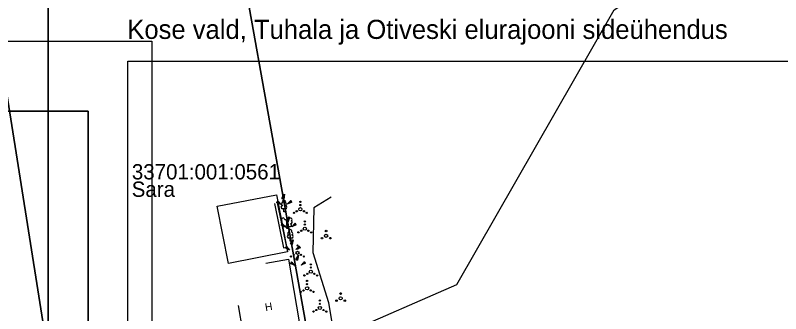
# Model space of a CAD drawing. Extents: x 554947 to 555436, y 6564938 to 6565792.
# Drawn here: x 555187.9 to 555307.9, y 6565612.2 to 6565659 of the extents above; entities that cross this region are included whole.
import ezdxf

# ---------------------------------------------------------------- set-up
doc = ezdxf.new("R2010")
doc.units = 0
for name, color, linetype in [('AED', 7, 'Continuous'), ('HALJASTUS', 7, 'Continuous'), ('HOONE', 7, 'Continuous'), ('Hoone Vare', 7, 'Continuous'), ('PIIR', 7, 'Continuous'), ('PR_SIDE', 7, 'Continuous'), ('PUU', 7, 'Continuous'), ('RELJEEF', 7, 'Continuous'), ('VORMISTUS_2', 7, 'Continuous'), ('VORMISTUS_3', 7, 'Continuous')]:
    doc.layers.add(name, color=color, linetype=linetype)

msp = doc.modelspace()

# ---------------------------------------------------------------- linework, layer by layer
at = {"layer": 'AED'}
msp.add_lwpolyline([(555228.56, 6565629.44), (555229.99, 6565622.5), (555230.48, 6565622.6), (555229.05, 6565629.54)], dxfattribs=at)
at = {"layer": 'HALJASTUS'}
msp.add_lwpolyline([(555237.45, 6565630.43), (555234.71, 6565628.77), (555234.59, 6565621.78), (555237.04, 6565613.92), (555237.94, 6565608.22), (555242.28, 6565610.46)], dxfattribs=at)
for centre, radius in [((555232.61, 6565629.7), 0.1), ((555232.05, 6565628.23), 0.1), ((555232.61, 6565628.55), 0.25), ((555232.61, 6565629.2), 0.1), ((555233.18, 6565628.23), 0.1), ((555231.61, 6565627.98), 0.1), ((555233.61, 6565627.98), 0.1), ((555233.31, 6565626.64), 0.1), ((555233.31, 6565626.14), 0.1), ((555232.31, 6565624.92), 0.1), ((555232.75, 6565625.17), 0.1), ((555233.31, 6565625.49), 0.25), ((555233.88, 6565625.17), 0.1), ((555234.31, 6565624.92), 0.1), ((555232.16, 6565622.86), 0.1), ((555232.16, 6565622.36), 0.1), ((555231.16, 6565621.14), 0.1), ((555231.59, 6565621.39), 0.1), ((555232.16, 6565621.71), 0.25), ((555232.72, 6565621.39), 0.1), ((555233.16, 6565621.14), 0.1), ((555234.25, 6565619.9), 0.1), ((555234.25, 6565618.75), 0.25), ((555234.25, 6565619.4), 0.1), ((555233.25, 6565618.17), 0.1), ((555233.69, 6565618.42), 0.1), ((555234.82, 6565618.42), 0.1), ((555235.25, 6565618.17), 0.1), ((555233.67, 6565616.15), 0.25), ((555233.67, 6565617.3), 0.1), ((555233.67, 6565616.8), 0.1), ((555232.67, 6565615.57), 0.1), ((555233.11, 6565615.82), 0.1), ((555234.24, 6565615.82), 0.1), ((555234.67, 6565615.57), 0.1), ((555235.67, 6565614.21), 0.1), ((555235.11, 6565612.74), 0.1), ((555235.67, 6565613.06), 0.25), ((555235.67, 6565613.71), 0.1), ((555236.24, 6565612.74), 0.1), ((555234.67, 6565612.49), 0.1), ((555236.67, 6565612.49), 0.1)]:
    msp.add_circle(centre, radius, dxfattribs=at)
at = {"layer": 'HOONE'}
msp.add_lwpolyline([(555227.21, 6565620.08), (555230.73, 6565620.69), (555232.44, 6565610.91), (555223.59, 6565609.46), (555222.94, 6565613.43)], dxfattribs=at)
at = {"layer": 'Hoone Vare'}
msp.add_lwpolyline([(555230.6, 6565621.87), (555221.34, 6565620.06), (555219.59, 6565629.02), (555228.86, 6565630.83)], close=True, dxfattribs=at)
at = {"layer": 'PIIR'}
msp.add_lwpolyline([(555193.24, 6565604.68), (555183.94, 6565663.24), (555223.17, 6565668.21), (555234.35, 6565605.6), (555225.47, 6565605.89), (555193.7, 6565602.7)], close=True, dxfattribs=at)
for points in [[(555374.15, 6565660.24), (555410.9, 6565638.65), (555418.94, 6565635.85), (555435.71, 6565632.72), (555428.83, 6565620.98), (555419.65, 6565609.54), (555361.56, 6565549.57), (555350.68, 6565540.44), (555343.81, 6565536.56), (555330.71, 6565538.85), (555251.24, 6565598.48), (555234.35, 6565605.6), (555223.17, 6565668.21)], [(555183.94, 6565663.24), (555193.24, 6565604.68), (555160.12, 6565598.86)]]:
    msp.add_lwpolyline(points, dxfattribs=at)
at = {"layer": 'PR_SIDE'}
msp.add_lwpolyline([(555232.4, 6565605.17), (555232.48, 6565605.3), (555234.36, 6565605.15), (555239.41, 6565608.98), (555257.15, 6565616.75), (555281.8, 6565659.83), (555291.68, 6565666.13), (555336.53, 6565656.68), (555340.55, 6565660.53)], dxfattribs=at)
at = {"layer": 'PUU'}
for p, q in [((555230.28, 6565628.63), (555229.8, 6565628.63)), ((555230.04, 6565628.15), (555230.04, 6565628.63)), ((555230.42, 6565628.15), (555230.04, 6565628.15)), ((555230.03, 6565625.84), (555230.47, 6565626.01)), ((555230.47, 6565625.5), (555230.29, 6565625.94)), ((555230.47, 6565626.01), (555230.91, 6565625.83)), ((555230.47, 6565625.5), (555230.65, 6565625.94)), ((555230.85, 6565625.5), (555230.47, 6565625.5)), ((555231.27, 6565624.03), (555230.79, 6565624.03)), ((555231.03, 6565623.55), (555231.03, 6565624.03)), ((555231.41, 6565623.55), (555231.03, 6565623.55))]:
    msp.add_line(p, q, dxfattribs=at)
msp.add_lwpolyline([(555230.47, 6565626.51), (555230.45, 6565626.43), (555230.45, 6565626.41), (555230.46, 6565626.38), (555230.48, 6565626.35), (555230.49, 6565626.33), (555230.47, 6565626.29), (555230.45, 6565626.24), (555230.44, 6565626.22), (555230.45, 6565626.2), (555230.46, 6565626.17), (555230.49, 6565626.11), (555230.5, 6565626.09), (555230.49, 6565626.07), (555230.48, 6565626.04), (555230.47, 6565626.01)], dxfattribs=at)
for centre, radius in [((555236.65, 6565625.13), 0.125), ((555235.99, 6565624.01), 0.125), ((555236.65, 6565624.38), 0.25), ((555237.3, 6565624.01), 0.125), ((555238.93, 6565615.32), 0.125), ((555238.28, 6565614.2), 0.125), ((555238.93, 6565614.57), 0.25), ((555239.58, 6565614.2), 0.125)]:
    msp.add_circle(centre, radius, dxfattribs=at)
for centre, radius, start, end in [((555229.87, 6565629.33), 0.233, 109.0217, 253.1415), ((555230.04, 6565629.67), 0.277, 332.5799, 207.4201), ((555230.21, 6565629.33), 0.233, 286.8508, 70.9859), ((555229.81, 6565628.87), 0.238, 90.0016, 269.3953), ((555230.28, 6565628.87), 0.238, 270.6047, 89.9984), ((555229.91, 6565626.92), 0.256, 111.5027, 232.5173), ((555229.91, 6565626.92), 0.256, 350.4856, 111.5002), ((555231.05, 6565626.91), 0.256, 67.6168, 188.6314), ((555231.05, 6565626.91), 0.256, 306.5997, 67.6143), ((555229.84, 6565626.51), 0.224, 111.4304, 274.4987), ((555229.94, 6565626.06), 0.237, 111.5014, 291.5004), ((555230.25, 6565626.67), 0.224, 308.5041, 111.5725), ((555230.47, 6565626.27), 0.237, 66.7655, 111.5015), ((555230.71, 6565626.66), 0.225, 67.7016, 230.5126), ((555231, 6565626.06), 0.237, 247.6166, 67.6155), ((555231.11, 6565626.5), 0.224, 264.6183, 67.6866), ((555230.86, 6565624.73), 0.233, 109.0217, 253.1415), ((555231.03, 6565625.07), 0.277, 332.5799, 207.4201), ((555231.2, 6565624.73), 0.233, 286.8508, 70.9859), ((555230.8, 6565624.27), 0.238, 90.0016, 269.3953), ((555231.27, 6565624.27), 0.238, 270.6047, 89.9984)]:
    msp.add_arc(centre, radius, start, end, dxfattribs=at)
at = {"layer": 'RELJEEF'}
for p, q in [((555229.72, 6565630.25), (555230.14, 6565630.89)), ((555229.97, 6565630.63), (555230.1, 6565630.69)), ((555230.14, 6565630.89), (555230, 6565630.14)), ((555230.02, 6565630.7), (555230.12, 6565630.74)), ((555230.07, 6565630.78), (555230.13, 6565630.8)), ((555230.12, 6565630.85), (555230.14, 6565630.86)), ((555229.08, 6565629.85), (555228.9, 6565629.61)), ((555229.59, 6565629.28), (555228.9, 6565629.61)), ((555228.91, 6565629.63), (555228.91, 6565629.61)), ((555228.95, 6565629.68), (555228.97, 6565629.58)), ((555229, 6565629.74), (555229.02, 6565629.56)), ((555229.04, 6565629.8), (555229.07, 6565629.53)), ((555229.08, 6565629.85), (555229.59, 6565629.28)), ((555229.08, 6565629.85), (555229.13, 6565629.5)), ((555229.08, 6565629.85), (555229.08, 6565629.85)), ((555229.14, 6565629.79), (555229.18, 6565629.48)), ((555229.2, 6565629.72), (555229.24, 6565629.45)), ((555229.26, 6565629.65), (555229.28, 6565629.51)), ((555229.28, 6565629.51), (555229.29, 6565629.42)), ((555229.32, 6565629.58), (555229.35, 6565629.4)), ((555229.38, 6565629.52), (555229.4, 6565629.37)), ((555229.72, 6565630.25), (555230.05, 6565630.39)), ((555229.72, 6565630.25), (555230, 6565630.14)), ((555229.72, 6565630.25), (555229.72, 6565630.25)), ((555229.77, 6565630.33), (555230.06, 6565630.45)), ((555229.79, 6565630.23), (555230.04, 6565630.33)), ((555229.82, 6565630.4), (555230.07, 6565630.51)), ((555229.85, 6565630.2), (555230.03, 6565630.27)), ((555229.87, 6565630.48), (555230, 6565630.53)), ((555229.92, 6565630.55), (555230.09, 6565630.63)), ((555229.92, 6565630.17), (555230.02, 6565630.21)), ((555229.99, 6565630.15), (555230, 6565630.15)), ((555230, 6565630.53), (555230.08, 6565630.57)), ((555230.56, 6565629.35), (555231.1, 6565629.89)), ((555231.27, 6565629.64), (555230.56, 6565629.35)), ((555230.85, 6565629.47), (555230.71, 6565629.5)), ((555230.94, 6565629.5), (555230.75, 6565629.54)), ((555230.89, 6565629.56), (555230.8, 6565629.58)), ((555231.1, 6565629.57), (555230.84, 6565629.62)), ((555231.19, 6565629.61), (555230.88, 6565629.67)), ((555231.02, 6565629.54), (555230.89, 6565629.56)), ((555231.27, 6565629.64), (555230.92, 6565629.71)), ((555231.23, 6565629.7), (555230.97, 6565629.75)), ((555231.19, 6565629.76), (555231.01, 6565629.79)), ((555231.15, 6565629.82), (555231.05, 6565629.84)), ((555231.11, 6565629.88), (555231.09, 6565629.88)), ((555231.27, 6565629.64), (555231.1, 6565629.89)), ((555231.27, 6565629.64), (555231.27, 6565629.64)), ((555229.44, 6565629.45), (555229.45, 6565629.35)), ((555229.5, 6565629.38), (555229.51, 6565629.32)), ((555229.56, 6565629.31), (555229.56, 6565629.29)), ((555230.6, 6565629.36), (555230.59, 6565629.37)), ((555230.69, 6565629.4), (555230.63, 6565629.41)), ((555230.77, 6565629.43), (555230.67, 6565629.45)), ((555230.42, 6565626.71), (555230.84, 6565627.35)), ((555230.62, 6565627.01), (555230.79, 6565627.08)), ((555230.67, 6565627.08), (555230.8, 6565627.14)), ((555230.84, 6565627.35), (555230.7, 6565626.59)), ((555230.72, 6565627.16), (555230.82, 6565627.2)), ((555230.77, 6565627.23), (555230.83, 6565627.26)), ((555230.82, 6565627.31), (555230.84, 6565627.32)), ((555229.78, 6565626.3), (555229.6, 6565626.06)), ((555230.29, 6565625.73), (555229.6, 6565626.06)), ((555229.61, 6565626.08), (555229.61, 6565626.06)), ((555229.65, 6565626.13), (555229.67, 6565626.03)), ((555229.7, 6565626.19), (555229.72, 6565626.01)), ((555229.74, 6565626.25), (555229.77, 6565625.98)), ((555229.78, 6565626.3), (555230.29, 6565625.73)), ((555229.78, 6565626.3), (555229.83, 6565625.95)), ((555229.78, 6565626.3), (555229.78, 6565626.3)), ((555229.84, 6565626.24), (555229.88, 6565625.93)), ((555229.9, 6565626.17), (555229.94, 6565625.9)), ((555229.96, 6565626.1), (555229.98, 6565625.96)), ((555229.98, 6565625.96), (555229.99, 6565625.87)), ((555230.02, 6565626.03), (555230.05, 6565625.85)), ((555230.08, 6565625.97), (555230.1, 6565625.82)), ((555230.14, 6565625.9), (555230.15, 6565625.8)), ((555230.42, 6565626.71), (555230.75, 6565626.85)), ((555230.42, 6565626.71), (555230.7, 6565626.59)), ((555230.42, 6565626.71), (555230.42, 6565626.71)), ((555230.47, 6565626.78), (555230.76, 6565626.9)), ((555230.49, 6565626.68), (555230.74, 6565626.79)), ((555230.52, 6565626.86), (555230.77, 6565626.96)), ((555230.55, 6565626.65), (555230.73, 6565626.73)), ((555230.57, 6565626.93), (555230.7, 6565626.99)), ((555230.62, 6565626.63), (555230.72, 6565626.67)), ((555230.69, 6565626.6), (555230.7, 6565626.61)), ((555230.7, 6565626.99), (555230.78, 6565627.02)), ((555231.26, 6565625.8), (555231.8, 6565626.34)), ((555231.97, 6565626.09), (555231.26, 6565625.8)), ((555231.47, 6565625.88), (555231.37, 6565625.9)), ((555231.55, 6565625.92), (555231.41, 6565625.95)), ((555231.64, 6565625.95), (555231.45, 6565625.99)), ((555231.59, 6565626.01), (555231.5, 6565626.03)), ((555231.8, 6565626.02), (555231.54, 6565626.07)), ((555231.89, 6565626.06), (555231.58, 6565626.12)), ((555231.72, 6565625.99), (555231.59, 6565626.01)), ((555231.97, 6565626.09), (555231.62, 6565626.16)), ((555231.93, 6565626.15), (555231.67, 6565626.2)), ((555231.89, 6565626.21), (555231.71, 6565626.24)), ((555231.85, 6565626.27), (555231.75, 6565626.29)), ((555231.81, 6565626.33), (555231.79, 6565626.33)), ((555231.97, 6565626.09), (555231.8, 6565626.34)), ((555231.97, 6565626.09), (555231.97, 6565626.09)), ((555230.2, 6565625.83), (555230.21, 6565625.77)), ((555230.26, 6565625.76), (555230.26, 6565625.74)), ((555231.3, 6565625.81), (555231.29, 6565625.82)), ((555231.39, 6565625.85), (555231.33, 6565625.86)), ((555231.07, 6565623.12), (555231.49, 6565623.76)), ((555231.27, 6565623.42), (555231.44, 6565623.49)), ((555231.32, 6565623.49), (555231.45, 6565623.55)), ((555231.49, 6565623.76), (555231.35, 6565623)), ((555231.36, 6565623.57), (555231.46, 6565623.61)), ((555231.41, 6565623.64), (555231.47, 6565623.67)), ((555231.46, 6565623.72), (555231.48, 6565623.73)), ((555230.42, 6565622.72), (555230.24, 6565622.48)), ((555230.93, 6565622.15), (555230.24, 6565622.48)), ((555230.25, 6565622.49), (555230.25, 6565622.47)), ((555230.29, 6565622.55), (555230.31, 6565622.45)), ((555230.34, 6565622.61), (555230.36, 6565622.42)), ((555230.38, 6565622.66), (555230.41, 6565622.39)), ((555230.42, 6565622.72), (555230.93, 6565622.15)), ((555230.42, 6565622.72), (555230.47, 6565622.37)), ((555230.42, 6565622.72), (555230.42, 6565622.72)), ((555230.48, 6565622.65), (555230.52, 6565622.34)), ((555230.54, 6565622.58), (555230.58, 6565622.32)), ((555230.6, 6565622.52), (555230.62, 6565622.38)), ((555230.62, 6565622.38), (555230.63, 6565622.29)), ((555230.66, 6565622.45), (555230.69, 6565622.26)), ((555230.72, 6565622.38), (555230.74, 6565622.24)), ((555230.78, 6565622.31), (555230.79, 6565622.21)), ((555231.07, 6565623.12), (555231.39, 6565623.26)), ((555231.07, 6565623.12), (555231.35, 6565623)), ((555231.07, 6565623.12), (555231.07, 6565623.12)), ((555231.12, 6565623.19), (555231.4, 6565623.31)), ((555231.13, 6565623.09), (555231.38, 6565623.2)), ((555231.17, 6565623.27), (555231.42, 6565623.37)), ((555231.2, 6565623.06), (555231.37, 6565623.14)), ((555231.22, 6565623.34), (555231.34, 6565623.4)), ((555231.27, 6565623.04), (555231.36, 6565623.08)), ((555231.33, 6565623.01), (555231.35, 6565623.02)), ((555231.34, 6565623.4), (555231.43, 6565623.43)), ((555231.9, 6565622.21), (555232.44, 6565622.76)), ((555232.61, 6565622.51), (555231.9, 6565622.21)), ((555232.03, 6565622.26), (555231.97, 6565622.28)), ((555232.11, 6565622.3), (555232.01, 6565622.32)), ((555232.19, 6565622.33), (555232.05, 6565622.36)), ((555232.28, 6565622.37), (555232.09, 6565622.4)), ((555232.23, 6565622.43), (555232.14, 6565622.45)), ((555232.44, 6565622.44), (555232.18, 6565622.49)), ((555232.53, 6565622.47), (555232.22, 6565622.53)), ((555232.36, 6565622.4), (555232.23, 6565622.43)), ((555232.61, 6565622.51), (555232.26, 6565622.57)), ((555232.57, 6565622.56), (555232.31, 6565622.62)), ((555232.53, 6565622.62), (555232.35, 6565622.66)), ((555232.49, 6565622.68), (555232.39, 6565622.7)), ((555232.45, 6565622.74), (555232.43, 6565622.74)), ((555232.61, 6565622.51), (555232.44, 6565622.76)), ((555232.61, 6565622.51), (555232.61, 6565622.51)), ((555230.84, 6565622.25), (555230.85, 6565622.18)), ((555230.9, 6565622.18), (555230.9, 6565622.16)), ((555231.89, 6565620.68), (555232.31, 6565621.32)), ((555231.94, 6565622.23), (555231.93, 6565622.23)), ((555232.14, 6565621.06), (555232.27, 6565621.12)), ((555232.31, 6565621.32), (555232.17, 6565620.57)), ((555232.19, 6565621.13), (555232.29, 6565621.17)), ((555232.24, 6565621.21), (555232.3, 6565621.23)), ((555232.29, 6565621.28), (555232.31, 6565621.29)), ((555231.25, 6565620.28), (555231.06, 6565620.04)), ((555231.75, 6565619.71), (555231.06, 6565620.04)), ((555231.07, 6565620.06), (555231.08, 6565620.04)), ((555231.12, 6565620.11), (555231.13, 6565620.01)), ((555231.16, 6565620.17), (555231.19, 6565619.99)), ((555231.2, 6565620.23), (555231.24, 6565619.96)), ((555231.25, 6565620.28), (555231.75, 6565619.71)), ((555231.25, 6565620.28), (555231.29, 6565619.93)), ((555231.25, 6565620.28), (555231.25, 6565620.28)), ((555231.31, 6565620.22), (555231.35, 6565619.91)), ((555231.37, 6565620.15), (555231.4, 6565619.88)), ((555231.43, 6565620.08), (555231.44, 6565619.94)), ((555231.44, 6565619.94), (555231.46, 6565619.85)), ((555231.48, 6565620.01), (555231.51, 6565619.83)), ((555231.54, 6565619.95), (555231.56, 6565619.8)), ((555231.6, 6565619.88), (555231.62, 6565619.78)), ((555231.89, 6565620.68), (555232.22, 6565620.82)), ((555231.89, 6565620.68), (555232.17, 6565620.57)), ((555231.89, 6565620.68), (555231.89, 6565620.68)), ((555231.94, 6565620.76), (555232.23, 6565620.88)), ((555231.96, 6565620.66), (555232.21, 6565620.76)), ((555231.99, 6565620.83), (555232.24, 6565620.94)), ((555232.02, 6565620.63), (555232.2, 6565620.7)), ((555232.04, 6565620.91), (555232.17, 6565620.96)), ((555232.09, 6565620.98), (555232.26, 6565621.06)), ((555232.09, 6565620.6), (555232.19, 6565620.64)), ((555232.16, 6565620.58), (555232.17, 6565620.58)), ((555232.17, 6565620.96), (555232.25, 6565621)), ((555232.73, 6565619.78), (555233.27, 6565620.32)), ((555233.44, 6565620.07), (555232.73, 6565619.78)), ((555232.94, 6565619.86), (555232.83, 6565619.88)), ((555233.02, 6565619.9), (555232.88, 6565619.93)), ((555233.1, 6565619.93), (555232.92, 6565619.97)), ((555233.05, 6565619.99), (555232.96, 6565620.01)), ((555233.27, 6565620), (555233, 6565620.05)), ((555233.35, 6565620.04), (555233.05, 6565620.1)), ((555233.19, 6565619.97), (555233.05, 6565619.99)), ((555233.44, 6565620.07), (555233.09, 6565620.14)), ((555233.4, 6565620.13), (555233.13, 6565620.18)), ((555233.36, 6565620.19), (555233.17, 6565620.22)), ((555233.32, 6565620.25), (555233.22, 6565620.27)), ((555233.28, 6565620.31), (555233.26, 6565620.31)), ((555233.44, 6565620.07), (555233.27, 6565620.32)), ((555233.44, 6565620.07), (555233.44, 6565620.07)), ((555231.66, 6565619.81), (555231.67, 6565619.75)), ((555231.72, 6565619.74), (555231.73, 6565619.72)), ((555232.77, 6565619.79), (555232.75, 6565619.8)), ((555232.85, 6565619.83), (555232.79, 6565619.84))]:
    msp.add_line(p, q, dxfattribs=at)
at = {"layer": 'VORMISTUS_2'}
for points in [[(554999.36, 6565654.91), (555209.36, 6565654.91), (555209.36, 6565357.91), (554999.36, 6565357.91)], [(555009.36, 6565368.91), (555199.36, 6565368.91), (555199.36, 6565643.91), (555009.36, 6565643.91)], [(555009.36, 6565643.91), (555199.36, 6565643.91), (555199.36, 6565368.91), (555009.36, 6565368.91)]]:
    msp.add_lwpolyline(points, close=True, dxfattribs=at)
at = {"layer": 'VORMISTUS_3'}
for points in [[(555193.07, 6565415.75), (555383.07, 6565415.75), (555383.07, 6565690.75), (555193.07, 6565690.75)], [(555193.07, 6565690.75), (555383.07, 6565690.75), (555383.07, 6565415.75), (555193.07, 6565415.75)], [(555370.57, 6565441.75), (555205.57, 6565441.75), (555205.57, 6565651.75), (555370.57, 6565651.75)]]:
    msp.add_lwpolyline(points, close=True, dxfattribs=at)

# ---------------------------------------------------------------- texts
at = {"layer": 'HOONE'}
msp.add_text('H', height=1.2, rotation=9.5306, dxfattribs=at).set_placement((555227.17, 6565612.57))
at = {"layer": 'PIIR'}
for s, p in [('33701:001:0561', (555206.21, 6565633.22)), ('Sara', (555206.18, 6565630.49))]:
    msp.add_text(s, height=2.4, dxfattribs=at).set_placement(p)
at = {"layer": 'VORMISTUS_3'}
msp.add_text('Kose vald, Tuhala ja Otiveski elurajooni sideühendus', height=3, rotation=360, dxfattribs=at).set_placement((555205.49, 6565655.26))

doc.saveas('drawing.dxf')
